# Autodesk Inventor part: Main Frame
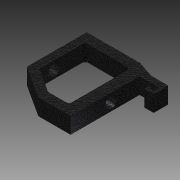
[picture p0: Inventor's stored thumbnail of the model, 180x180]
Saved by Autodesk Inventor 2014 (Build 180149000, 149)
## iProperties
Created: 2009-03
Part Number: Main Frame
Document SubType Name: Modeling
Designer: tangg
Density: 7.25 g/cm^3
Material: Cast Iron
Mass: 64.2851 g
Surface Area: 53.7917 cm^2
Volume: 8.86691 cm^3
Appearance: Black Cast
Author: tangg
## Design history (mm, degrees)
sketch "Sketch1"
  geometry: L1 (0, 25)-(33, 25); L2 (40, 17.692)-(40, -25); L3 (40, -25)-(20, -25); L4 (0, -12.066)-(0, 25); L5 (7, 19)-(31, 19); L6 (33, 17)-(33, -17); L7 (31, -19)-(20.59, -19); L8 (5, -8.211)-(5, 17); L9 (33, 25)-(43.137, 21.604); L10 (43.137, 21.604)-(53.5, 21.604); L11 (54, 21.104)-(54, 12.914); L12 (53.5, 12.414)-(52.628, 12.414); L13 (52, 14.414)-(52, 17.692); L14 (52, 17.692)-(40, 17.692); L15 (5.914, -9.89)-(19.504, -18.679); L16 (20, -25)-(0, -12.066); L17 (48.5, 15.48)-(49.5, 15.48); L18 (50, 14.98)-(50, 14.414); L19 (48, 12.914)-(48, 14.98); L20 (50, 14.414)-(52, 14.414); L21 (52.628, 12.414)-(48.5, 12.414); A1 r 2 centre (7, 17) between (7, 19) and (5, 17); A2 r 2 centre (31, 17) between (33, 17) and (31, 19); A3 r 2 centre (31, -17) between (31, -19) and (33, -17); A4 r 2 centre (7, -8.211) between (5, -8.211) and (5.914, -9.89); A5 r 2 centre (20.59, -17) between (19.504, -18.679) and (20.59, -19); A6 r 0.5 centre (48.5, 14.98) between (48.5, 15.48) and (48, 14.98); A7 r 0.5 centre (49.5, 14.98) between (50, 14.98) and (49.5, 15.48); A8 r 0.5 centre (48.5, 12.914) between (48, 12.914) and (48.5, 12.414); A9 r 0.5 centre (53.5, 12.914) between (53.5, 12.414) and (54, 12.914); A10 r 0.5 centre (53.5, 21.104) between (54, 21.104) and (53.5, 21.604); 4 further points
  constraints: 43 end point, 20 point on circle, 20 tangent, 10 centre point, 9 parallel, 6 equal radius, 6 perpendicular, 5 point on line, 4 horizontal, 1 coincident
  dimensions: "d0" = 40 distance between parallel lines of L2 L4; "d1" = 50 distance between parallel lines of L3 L1; "d2" = 6 distance between parallel lines of L5 L1; "d3" = 6 distance between parallel lines of L3 L7; "d4" = 5 distance between parallel lines of L4 L8; "d5" = 7 distance between parallel lines of L2 L6; "d6" = 2 radius of A1; "d18" = 2 radius of A4; "d19" = 0.5 radius of A6; "d20" = 0.5 radius of A7; "d21" = 2 distance between parallel lines of L21 L20; "d22" = 2 distance between parallel lines of L18 L19; "d24" = 2 distance between parallel lines of L11 L13; "d25" = 6 distance between parallel lines of L11 L19; "d26" = 14 distance between parallel lines of L11 L2
extrude "Extrusion1" new body sketch "Sketch1" stored distance "d7" = 10; taper "d8" = 0 deg
sketch "Sketch5"
  geometry: C1 r 3.525 at (0, 0); 1 further point
  constraints: 1 centre point, 1 coincident
  dimensions: "d27" = 7.05 diameter of C1
extrude "Extrusion5" cut sketch "Sketch5" stored distance "d28" = 10; taper "d29" = 0 deg
fillet "Fillet1" dims "d15" = 1
sketch "Sketch2"
  geometry: C1 r 3.5 at (-5, 12.066); 1 further point
  constraints: 1 centre point, 1 coincident
  dimensions: "d9" = 7 diameter of C1
extrude "Extrusion2" cut sketch "Sketch2" stored distance "d10" = 8; taper "d11" = 0 deg
body "Solid1"
